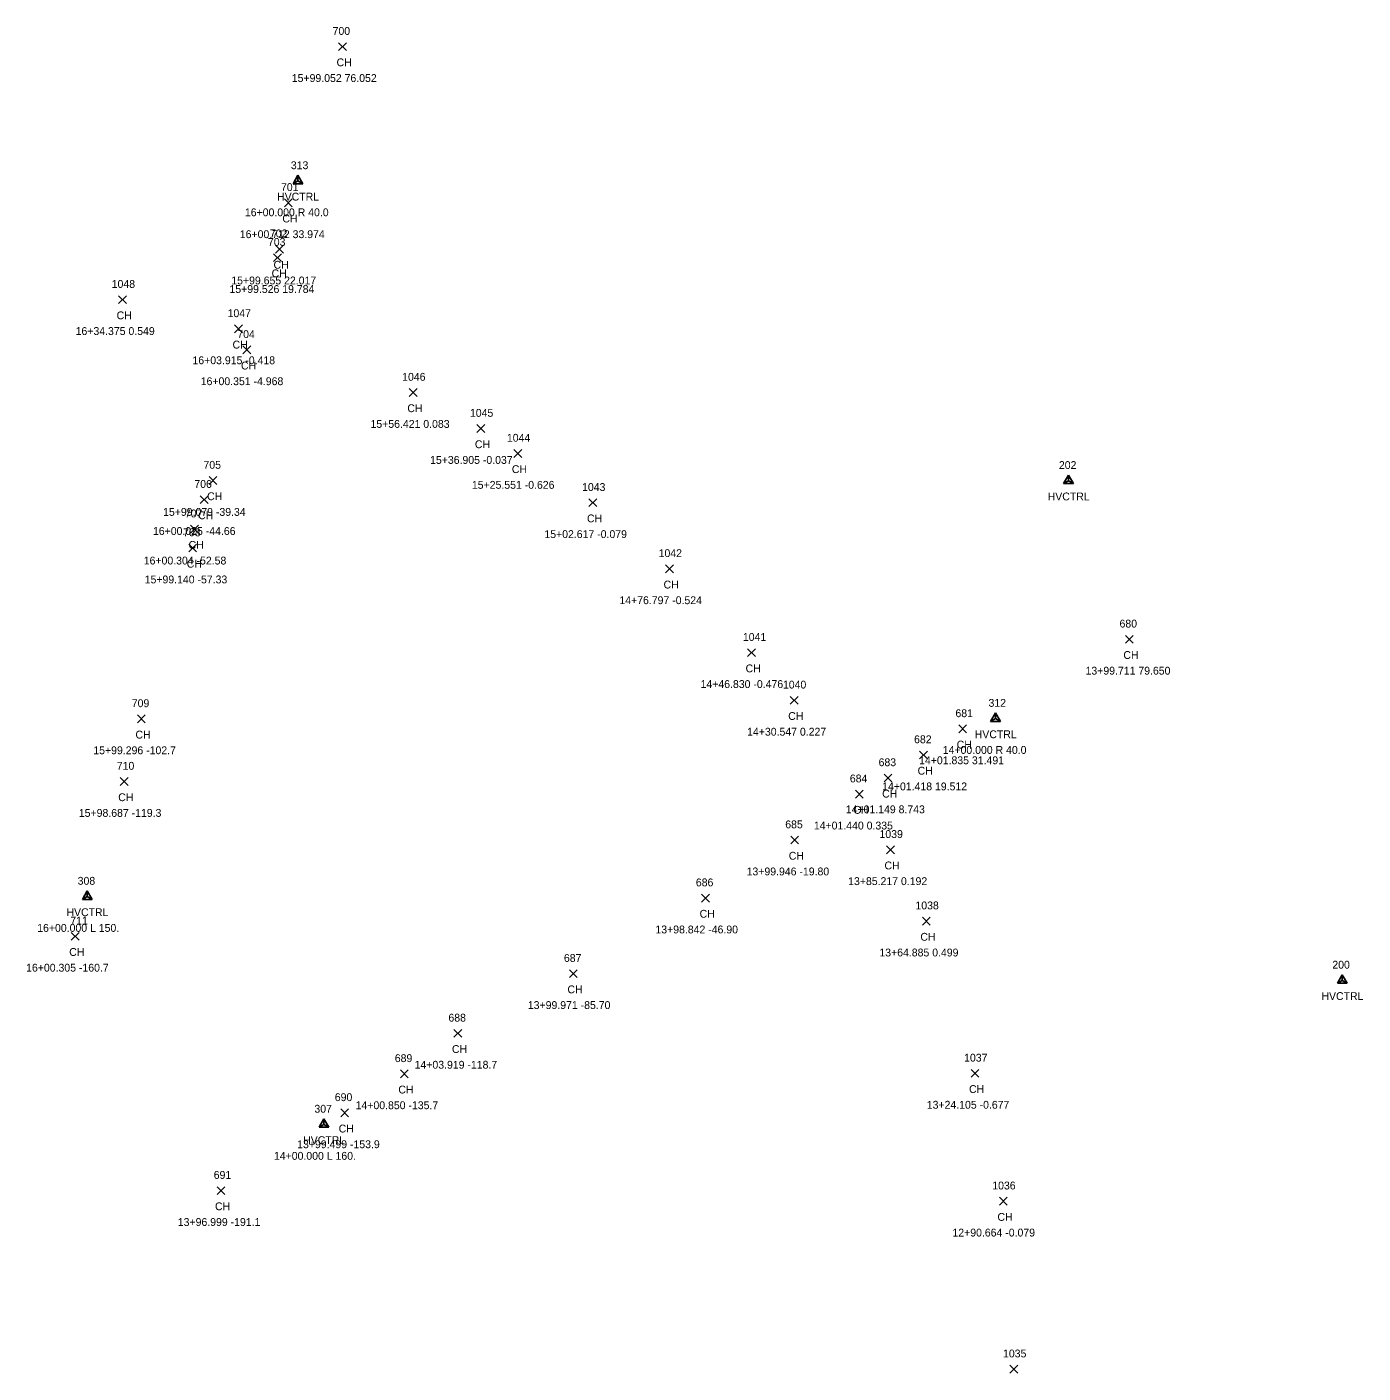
# Model space of a CAD drawing. Extents: x 89316 to 92454, y 84175 to 86051.
# Drawn here: x 90704.5 to 91045.1, y 84905.4 to 85248.6 of the extents above; entities that cross this region are included whole.
import ezdxf

# ---------------------------------------------------------------- set-up
doc = ezdxf.new("R2010")
doc.units = 0
for name, color, linetype in [('C_A', 7, 'Continuous'), ('C_C', 7, 'Continuous'), ('C_I', 7, 'Continuous'), ('CPSM', 7, 'Continuous'), ('L_A', 7, 'Continuous'), ('L_C', 7, 'Continuous'), ('L_I', 7, 'Continuous'), ('L_TIC', 7, 'Continuous')]:
    doc.layers.add(name, color=color, linetype=linetype)

msp = doc.modelspace()

# ---------------------------------------------------------------- linework, layer by layer
at = {"layer": 'CPSM'}
for p, q in [((90772.36, 85208.58), (90773.61, 85210.75)), ((90772.36, 85208.58), (90773.61, 85209.3)), ((90774.86, 85208.58), (90773.61, 85210.75)), ((90773.61, 85209.3), (90773.61, 85210.75)), ((90773.61, 85209.3), (90773.61, 85209.3)), ((90773.61, 85209.3), (90774.86, 85208.58)), ((90772.36, 85208.58), (90774.86, 85208.58)), ((90968.74, 85132.16), (90969.99, 85134.32)), ((90971.24, 85132.16), (90969.99, 85134.32)), ((90969.99, 85132.88), (90969.99, 85134.32)), ((90968.74, 85132.16), (90969.99, 85132.88)), ((90968.74, 85132.16), (90971.24, 85132.16)), ((90969.99, 85132.88), (90969.99, 85132.88)), ((90969.99, 85132.88), (90971.24, 85132.16)), ((90950.15, 85071.55), (90951.4, 85073.71)), ((90950.15, 85071.55), (90951.41, 85072.27)), ((90950.15, 85071.55), (90952.65, 85071.55)), ((90952.65, 85071.55), (90951.4, 85073.71)), ((90951.41, 85072.27), (90951.4, 85073.71)), ((90951.41, 85072.27), (90951.41, 85072.27)), ((90951.41, 85072.27), (90952.65, 85071.55)), ((90718.67, 85026.19), (90719.92, 85028.35)), ((90718.67, 85026.19), (90719.92, 85026.91)), ((90721.17, 85026.19), (90719.92, 85028.35)), ((90719.92, 85026.91), (90719.92, 85028.35)), ((90719.92, 85026.91), (90719.92, 85026.91)), ((90719.92, 85026.91), (90721.17, 85026.19)), ((90718.67, 85026.19), (90721.17, 85026.19)), ((91038.52, 85004.8), (91039.77, 85006.97)), ((91041.02, 85004.8), (91039.77, 85006.97)), ((91039.77, 85005.53), (91039.77, 85006.97)), ((91038.52, 85004.8), (91039.77, 85005.53)), ((91038.52, 85004.8), (91041.02, 85004.8)), ((91039.77, 85005.53), (91039.77, 85005.53)), ((91039.77, 85005.53), (91041.02, 85004.8)), ((90779, 84968.09), (90780.25, 84970.26)), ((90779, 84968.09), (90780.25, 84968.81)), ((90781.5, 84968.09), (90780.25, 84970.26)), ((90780.25, 84968.81), (90780.25, 84970.26)), ((90780.25, 84968.81), (90780.25, 84968.81)), ((90780.25, 84968.81), (90781.5, 84968.09)), ((90779, 84968.09), (90781.5, 84968.09))]:
    msp.add_line(p, q, dxfattribs=at)
at = {"layer": 'L_TIC'}
for points in [[(90783.98, 85242.53), (90785.98, 85244.53)], [(90785.98, 85242.53), (90783.98, 85244.53)], [(90770.16, 85202.73), (90772.16, 85204.73)], [(90772.16, 85202.73), (90770.16, 85204.73)], [(90767.91, 85190.93), (90769.91, 85192.93)], [(90769.91, 85190.93), (90767.91, 85192.93)], [(90767.41, 85188.75), (90769.41, 85190.75)], [(90769.41, 85188.75), (90767.41, 85190.75)], [(90727.92, 85178.04), (90729.92, 85180.04)], [(90729.92, 85178.04), (90727.92, 85180.04)], [(90757.46, 85170.59), (90759.46, 85172.59)], [(90759.46, 85170.59), (90757.46, 85172.59)], [(90759.6, 85165.25), (90761.6, 85167.25)], [(90761.6, 85165.25), (90759.6, 85167.25)], [(90802, 85154.37), (90804, 85156.37)], [(90804, 85154.37), (90802, 85156.37)], [(90819.22, 85145.19), (90821.22, 85147.19)], [(90821.22, 85145.19), (90819.22, 85147.19)], [(90828.64, 85138.84), (90830.64, 85140.84)], [(90830.64, 85138.84), (90828.64, 85140.84)], [(90750.98, 85131.94), (90752.98, 85133.94)], [(90752.98, 85131.94), (90750.98, 85133.94)], [(90748.7, 85127.07), (90750.7, 85129.07)], [(90750.7, 85127.07), (90748.7, 85129.07)], [(90847.79, 85126.28), (90849.79, 85128.28)], [(90849.79, 85126.28), (90847.79, 85128.28)], [(90746.25, 85119.54), (90748.25, 85121.54)], [(90748.25, 85119.54), (90746.25, 85121.54)], [(90745.79, 85114.73), (90747.79, 85116.73)], [(90747.79, 85114.73), (90745.79, 85116.73)], [(90867.31, 85109.43), (90869.31, 85111.43)], [(90869.31, 85109.43), (90867.31, 85111.43)], [(90984.5, 85091.47), (90986.5, 85093.47)], [(90986.5, 85091.47), (90984.5, 85093.47)], [(90888.21, 85088.06), (90890.21, 85090.06)], [(90890.21, 85088.06), (90888.21, 85090.06)], [(90899.08, 85075.92), (90901.08, 85077.92)], [(90901.08, 85075.92), (90899.08, 85077.92)], [(90732.72, 85071.18), (90734.72, 85073.18)], [(90734.72, 85071.18), (90732.72, 85073.18)], [(90942.03, 85068.63), (90944.03, 85070.63)], [(90944.03, 85068.63), (90942.03, 85070.63)], [(90932.05, 85061.98), (90934.05, 85063.98)], [(90934.05, 85061.98), (90932.05, 85063.98)], [(90923.01, 85056.13), (90925.01, 85058.13)], [(90925.01, 85056.13), (90923.01, 85058.13)], [(90728.34, 85055.22), (90730.34, 85057.22)], [(90730.34, 85055.22), (90728.34, 85057.22)], [(90915.68, 85052), (90917.68, 85054)], [(90917.68, 85052), (90915.68, 85054)], [(90899.22, 85040.3), (90901.22, 85042.3)], [(90901.22, 85040.3), (90899.22, 85042.3)], [(90923.61, 85037.83), (90925.61, 85039.83)], [(90925.61, 85037.83), (90923.61, 85039.83)], [(90876.5, 85025.51), (90878.5, 85027.51)], [(90878.5, 85025.51), (90876.5, 85027.51)], [(90932.76, 85019.64), (90934.76, 85021.64)], [(90934.76, 85019.64), (90932.76, 85021.64)], [(90715.83, 85015.77), (90717.83, 85017.77)], [(90717.83, 85015.77), (90715.83, 85017.77)], [(90842.81, 85006.24), (90844.81, 85008.24)], [(90844.81, 85006.24), (90842.81, 85008.24)], [(90813.38, 84991.03), (90815.38, 84993.03)], [(90815.38, 84991.03), (90813.38, 84993.03)], [(90799.72, 84980.71), (90801.72, 84982.71)], [(90801.72, 84980.71), (90799.72, 84982.71)], [(90945.17, 84980.83), (90947.17, 84982.83)], [(90947.17, 84980.83), (90945.17, 84982.83)], [(90784.51, 84970.77), (90786.51, 84972.77)], [(90786.51, 84970.77), (90784.51, 84972.77)], [(90753, 84950.95), (90755, 84952.95)], [(90755, 84950.95), (90753, 84952.95)], [(90952.4, 84948.25), (90954.4, 84950.25)], [(90954.4, 84948.25), (90952.4, 84950.25)], [(90955.08, 84905.44), (90957.08, 84907.44)], [(90957.08, 84905.44), (90955.08, 84907.44)]]:
    msp.add_lwpolyline(points, dxfattribs=at)

# ---------------------------------------------------------------- texts
at = {"layer": 'C_A'}
for p in [(90768.3, 85204.3), (90964.69, 85127.88), (90946.1, 85067.27), (90714.62, 85021.91), (91034.46, 85000.53), (90774.94, 84963.81)]:
    msp.add_text('HVCTRL', height=2, dxfattribs=at).set_placement(p)
at = {"layer": 'C_C'}
for s, p in [('16+00.000 R 40.0', (90760.1, 85200.3)), ('14+00.000 R 40.0', (90937.95, 85063.27)), ('16+00.000 L 150.', (90707.17, 85017.91)), ('14+00.000 L 160.', (90767.5, 84959.81))]:
    msp.add_text(s, height=2, dxfattribs=at).set_placement(p)
at = {"layer": 'C_I'}
for s, p in [('313', (90771.81, 85212.3)), ('202', (90967.55, 85135.88)), ('312', (90949.61, 85075.27)), ('308', (90717.48, 85029.91)), ('200', (91037.24, 85008.53)), ('307', (90777.81, 84971.81))]:
    msp.add_text(s, height=2, dxfattribs=at).set_placement(p)
at = {"layer": 'L_A'}
for p in [(90783.46, 85238.53), (90769.65, 85198.73), (90767.4, 85186.93), (90766.9, 85184.75), (90727.41, 85174.04), (90756.95, 85166.59), (90759.09, 85161.25), (90801.49, 85150.37), (90818.71, 85141.19), (90828.13, 85134.84), (90750.47, 85127.94), (90748.19, 85123.07), (90847.28, 85122.28), (90745.74, 85115.54), (90745.28, 85110.73), (90866.8, 85105.43), (90983.99, 85087.47), (90887.7, 85084.06), (90898.56, 85071.92), (90732.21, 85067.18), (90941.51, 85064.63), (90931.54, 85057.98), (90727.82, 85051.22), (90922.5, 85052.13), (90915.17, 85048), (90898.71, 85036.3), (90923.1, 85033.83), (90875.98, 85021.51), (90932.25, 85015.64), (90715.32, 85011.77), (90842.3, 85002.24), (90812.86, 84987.03), (90799.21, 84976.71), (90944.65, 84976.83), (90783.99, 84966.77), (90752.48, 84946.95), (90951.89, 84944.25)]:
    msp.add_text('CH', height=2, dxfattribs=at).set_placement(p)
at = {"layer": 'L_C'}
for s, p in [('15+99.052 76.052', (90772.05, 85234.53)), ('16+00.712 33.974', (90758.8, 85194.73)), ('15+99.655 22.017', (90756.63, 85182.93)), ('15+99.526 19.784', (90756.16, 85180.75)), ('16+34.375 0.549', (90716.96, 85170.04)), ('16+03.915 -0.418', (90746.74, 85162.59)), ('16+00.351 -4.968', (90748.84, 85157.25)), ('15+56.421 0.083', (90792.11, 85146.37)), ('15+36.905 -0.037', (90807.29, 85137.19)), ('15+25.551 -0.626', (90817.95, 85130.84)), ('15+99.079 -39.34', (90739.25, 85123.94)), ('16+00.025 -44.66', (90736.67, 85119.07)), ('15+02.617 -0.079', (90836.42, 85118.28)), ('16+00.304 -52.58', (90734.32, 85111.54)), ('15+99.140 -57.33', (90734.56, 85106.73)), ('14+76.797 -0.524', (90855.54, 85101.43)), ('13+99.711 79.650', (90974.34, 85083.47)), ('14+46.830 -0.476', (90876.23, 85080.06)), ('14+30.547 0.227', (90888.09, 85067.92)), ('15+99.296 -102.7', (90721.47, 85063.18)), ('14+01.835 31.491', (90931.92, 85060.63)), ('14+01.418 19.512', (90922.51, 85053.98)), ('15+98.687 -119.3', (90717.78, 85047.22)), ('14+01.149 8.743', (90913.24, 85048.13)), ('14+01.440 0.335', (90905.1, 85044)), ('13+99.946 -19.80', (90887.96, 85032.3)), ('13+85.217 0.192', (90913.84, 85029.83)), ('13+98.842 -46.90', (90864.72, 85017.51)), ('13+64.885 0.499', (90921.8, 85011.64)), ('16+00.305 -160.7', (90704.34, 85007.77)), ('13+99.971 -85.70', (90832.21, 84998.24)), ('14+03.919 -118.7', (90803.35, 84983.03)), ('14+00.850 -135.7', (90788.32, 84972.71)), ('13+24.105 -0.677', (90933.88, 84972.83)), ('13+99.499 -153.9', (90773.42, 84962.77)), ('13+96.999 -191.1', (90743, 84942.95)), ('12+90.664 -0.079', (90940.42, 84940.25))]:
    msp.add_text(s, height=2, dxfattribs=at).set_placement(p)
at = {"layer": 'L_I'}
for s, p in [('700', (90782.45, 85246.53)), ('701', (90769.29, 85206.73)), ('702', (90766.47, 85194.93)), ('703', (90765.97, 85192.75)), ('1048', (90726.15, 85182.04)), ('1047', (90755.69, 85174.59)), ('704', (90758.16, 85169.25)), ('1046', (90800.18, 85158.37)), ('1045', (90817.45, 85149.19)), ('1044', (90826.87, 85142.84)), ('705', (90749.54, 85135.94)), ('706', (90747.21, 85131.07)), ('1043', (90846.02, 85130.28)), ('707', (90744.81, 85123.54)), ('708', (90744.35, 85118.73)), ('1042', (90865.54, 85113.43)), ('680', (90983, 85095.47)), ('1041', (90887.01, 85092.06)), ('1040', (90897.22, 85079.92)), ('709', (90731.27, 85075.18)), ('681', (90941.18, 85072.63)), ('682', (90930.64, 85065.98)), ('710', (90727.45, 85059.22)), ('683', (90921.6, 85060.13)), ('684', (90914.27, 85056)), ('685', (90897.81, 85044.3)), ('1039', (90921.83, 85041.83)), ('686', (90875.03, 85029.51)), ('1038', (90930.99, 85023.64)), ('711', (90715.6, 85019.77)), ('687', (90841.4, 85010.24)), ('688', (90811.97, 84995.03)), ('689', (90798.3, 84984.71)), ('1037', (90943.39, 84984.83)), ('690', (90783.01, 84974.77)), ('691', (90752.15, 84954.95)), ('1036', (90950.57, 84952.25)), ('1035', (90953.31, 84909.44))]:
    msp.add_text(s, height=2, dxfattribs=at).set_placement(p)

doc.saveas('drawing.dxf')
